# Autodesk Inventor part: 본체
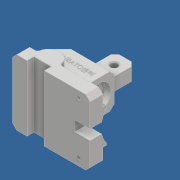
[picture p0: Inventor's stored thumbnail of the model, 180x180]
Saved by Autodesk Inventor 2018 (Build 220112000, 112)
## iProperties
Created: 2022-08
Part Number: 본체
Material: 일반
Document SubType Name: Modeling
Designer: home
Density: 1 g/cm^3
Appearance: 기본값
Author: home
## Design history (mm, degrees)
sketch "스케치1"
  geometry: L1 (63, 0)-(63, 15); L2 (-27, 15)-(-27, 0); L3 (63, 15)-(13, 15); L4 (-13, 15)-(-27, 15); L5 (10, 0)-(10, 8); L6 (10, 8)-(-10, 8); L7 (-10, 8)-(-10, 0); L8 (-27, 0)-(-10, 0); L9 (10, 0)-(63, 0); A1 r 13 centre (0, 15) between (13, 15) and (-13, 15); 2 further points
  constraints: 18 end point, 8 parallel, 2 horizontal, 2 perpendicular, 2 point on circle, 2 vertical alignment, 1 centre point, 1 midpoint
  dimensions: "d0" = 15 distance of L2.start L2.end; "d1" = 27 distance from line of L2 point (0, 0); "d2" = 90 distance of L2.end L1.start; "d3" = 26 diameter of A1; "d4" = 8 distance of L6.end L7.end; "d5" = 20 distance of L5.end L6.end; "d6" = 53 distance between parallel lines of L1 L5; "d7" = 15 distance between parallel lines of L3 L9; "d8" = 15 distance from line of point (0, 0) L3; "d9" = 50 distance from line of L3.end L1
extrude "돌출1" new body sketch "스케치1" stored distance "d10" = 76; taper "d11" = 0 deg
sketch "스케치2"
  geometry: L1 (-27, 0)-(-27, 15) reference; L2 (-27, 15)-(-13, 15) reference; L3 (13, 15)-(63, 15) reference; L4 (63, 15)-(63, 0) reference; L5 (63, 0)-(10, 0) reference; L6 (10, 0)-(10, 8) reference; L7 (10, 8)-(-10, 8) reference; L8 (-10, 8)-(-10, 0) reference; L9 (-10, 0)-(-27, 0) reference; L10 (-27, 0)-(-27, 15) reference; L11 (-27, 15)-(31, 15); L12 (31, 15)-(31, 60); L13 (31, 60)-(-27, 60); L14 (-27, 60)-(-27, 15); L15 (13, 15)-(63, 15) reference; L16 (63, 15)-(31, 15); L17 (31, 15)-(31, 19); L18 (31, 19)-(63, 19); L19 (63, 19)-(63, 15); A1 r 13 centre (0, 15) between (13, 15) and (-13, 15) reference; 1 further point
  constraints: 16 end point, 3 parallel, 2 horizontal, 1 perpendicular, 1 point on line
  dimensions: "d13" = 45 distance of L13.end L1.end; "d15" = 32 distance between parallel lines of L12 L4; "d16" = 19 distance between parallel lines of L18 L5; "d65" = 90 deg angle of L3 L14
extrude "돌출2" join sketch "스케치2" stored distance "d17" = 40; taper "d18" = 0 deg
chamfer "모따기1" distance "d19" = 18; stored, may be unused: second distance "d20" = 2, angle "d21" = 45 deg
sketch "스케치3"
  geometry: L1 (-9, 60)-(-27, 42) reference; L2 (-9, 60)-(31, 60) reference; L3 (31, 60)-(31, 19) reference; L4 (31, 19)-(63, 19) reference; L5 (63, 19)-(63, 15) reference; L6 (13, 15)-(63, 15) reference; L7 (-27, 15)-(-13, 15) reference; L8 (-27, 15)-(-27, 42) reference; L9 (2, 60)-(26, 60); L10 (26, 60)-(26, 85); L11 (21, 90)-(7, 90); L12 (2, 85)-(2, 60); L13 (2, 85)-(7, 90); L14 (21, 90)-(26, 85); A1 r 13 centre (0, 15) between (13, 15) and (-13, 15) reference; 3 further points
  constraints: 12 end point, 5 point on line, 2 parallel, 1 horizontal, 1 perpendicular
  dimensions: "d22" = 5 distance between parallel lines of L10 L3; "d23" = 24 distance of point (26, 90) point (2, 90); "d24" = 30 distance of point (2, 90) L9.start; "d25" = 5 distance of L12.start point (2, 90); "d26" = 5 distance of L11.end point (2, 90) (= d25); "d27" = 5 distance of L11.start point (26, 90) (= d25); "d28" = 5 distance of L10.end point (26, 90) (= d27)
extrude "돌출3" join sketch "스케치3" stored distance "d31" = 15; taper "d32" = 0 deg
chamfer "모따기2" distance "d33" = 5; stored, may be unused: second distance "d34" = 2, angle "d35" = 45 deg
sketch "스케치4"
  geometry: L1 (35, 41)-(40, 36) reference; L2 (35, 41)-(5, 41) reference; L3 (0, 36)-(5, 41) reference; L4 (0, 0)-(0, 36) reference; L5 (0, 0)-(40, 0) reference; L6 (40, 36)-(40, 0) reference; L7 (-18, -19)-(58, -19) reference; 3 further points
  constraints: 1 midpoint, 1 vertical alignment
  dimensions: "d36" = 42 distance from line of point (20, 23) L7
hole "구멍1" sketch "스케치4" at (20, 23) diameter "d37" = 20; stored, may be unused: countersink angle "d41" = 90 deg, drill point angle "d43" = 118 deg; dims "d38" = 6, "d39" = 29, "d40" = 7, "d42" = 8
sketch "스케치5"
  geometry: L1 (0, 0)-(-76, 0) reference; L2 (-44, 0)-(-32, 0); L3 (-32, 0)-(-32, 13.627); L4 (-44, 13.627)-(-44, 0); L5 (-76, 0)-(0, 0) reference; L6 (0, 15)-(0, 0) reference; L7 (-18, 15)-(0, 15) reference; L8 (-18, 19)-(-18, 15) reference; L9 (-18, 19)-(-58, 19) reference; L10 (-58, 15)-(-58, 19) reference; L11 (-76, 15)-(-58, 15) reference; L12 (-76, 0)-(-76, 15) reference; L13 (-55.664, 19)-(-20.336, 19); C1 r 14.5 at (-38, 42) reference; C2 r 10 at (-38, 42) reference; A1 r 29 centre (-38, 42) between (-55.664, 19) and (-44, 13.627); A2 r 29 centre (-38, 42) between (-32, 13.627) and (-20.336, 19); 3 further points
  constraints: 8 end point, 4 point on circle, 3 point on line, 2 centre point, 1 coincident, 1 horizontal, 1 midpoint, 1 parallel, 1 perpendicular, 1 vertical alignment
  dimensions: "d45" = 12 distance between parallel lines of L3 L4; "d66" = 29 radius of A2; "d67" = 29 radius of A1; "d68" = 32 distance between parallel lines of L6 L3; "d69" = 16.34201 distance from line of point (-38, 16.342) L1
extrude "돌출4" cut sketch "스케치5" distance "d46" = 18; taper "d47" = 0 deg
chamfer "모따기3" distance "d48" = 5; stored, may be unused: second distance "d49" = 2, angle "d50" = 45 deg
sketch "스케치6"
  geometry: L1 (26, 60)-(26, 85) reference; L2 (10, 0)-(58, 0) reference; C1 r 4 at (14, 77); 1 further point
  constraints: 1 centre point
  dimensions: "d51" = 8 diameter of C1; "d52" = 12 distance from line of C1.centre L1; "d53" = 77 distance from line of L2 C1.centre
extrude "돌출5" cut sketch "스케치6" extent not by distance; stored distance "d54" = 18; taper "d55" = 0 deg
sketch "스케치7"
  geometry: L1 (50, -13)-(50, 0) reference; L2 (-40, 10)-(-40, 30) reference; L3 (11, 10)-(11, 30) reference; L4 (32, 2.336)-(32, 37.664) reference; L5 (45, -18)-(0, -18) reference; A1 r 10 centre (-40, 20) between (-40, 10) and (-40, 30) reference; 2 further points
  dimensions: "d56" = 13 distance from line of point (37, -10) L1; "d57" = 8 distance from line of point (37, -10) L5
hole "구멍2" sketch "스케치7" at (37, -10) diameter "d58" = 4.5; stored, may be unused: countersink angle "d62" = 90 deg, drill point angle "d64" = 118 deg; dims "d59" = 6, "d60" = 8, "d61" = 4.4, "d63" = 8
sketch "스케치8"
  geometry: L1 (31, 60)-(-9, 60) reference; L2 (31, 19)-(31, 55) reference; 2 further points
  constraints: 1 other
  dimensions: "d70" = 18 distance from line of point (5, 42) L1; "d71" = 26 distance from line of L2 point (5, 42)
feature "엠보싱1" sketch "스케치8" dims "d72" = 0.5, "d73" = 0
fillet "모깎기1" dims "d74" = 3
chamfer "모따기4" distance "d75" = 1; stored, may be unused: second distance "d76" = 2, angle "d77" = 45 deg
node "솔리드1"
mirror "미러1"
node "투영된 루프1"
node "투영된 루프2"
node "투영된 루프3"
node "투영된 루프4"
node "투영된 루프5"
node "투영된 루프6"
other parameters: "d44" = 58
